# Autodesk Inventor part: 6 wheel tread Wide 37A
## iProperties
Created: 2009-03
Part Number: 6 wheel tread Wide 37A
Document SubType Name: Modeling
Designer: Pat
Density: 1 g/cm^3
Author: Pat
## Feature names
1. Base1
